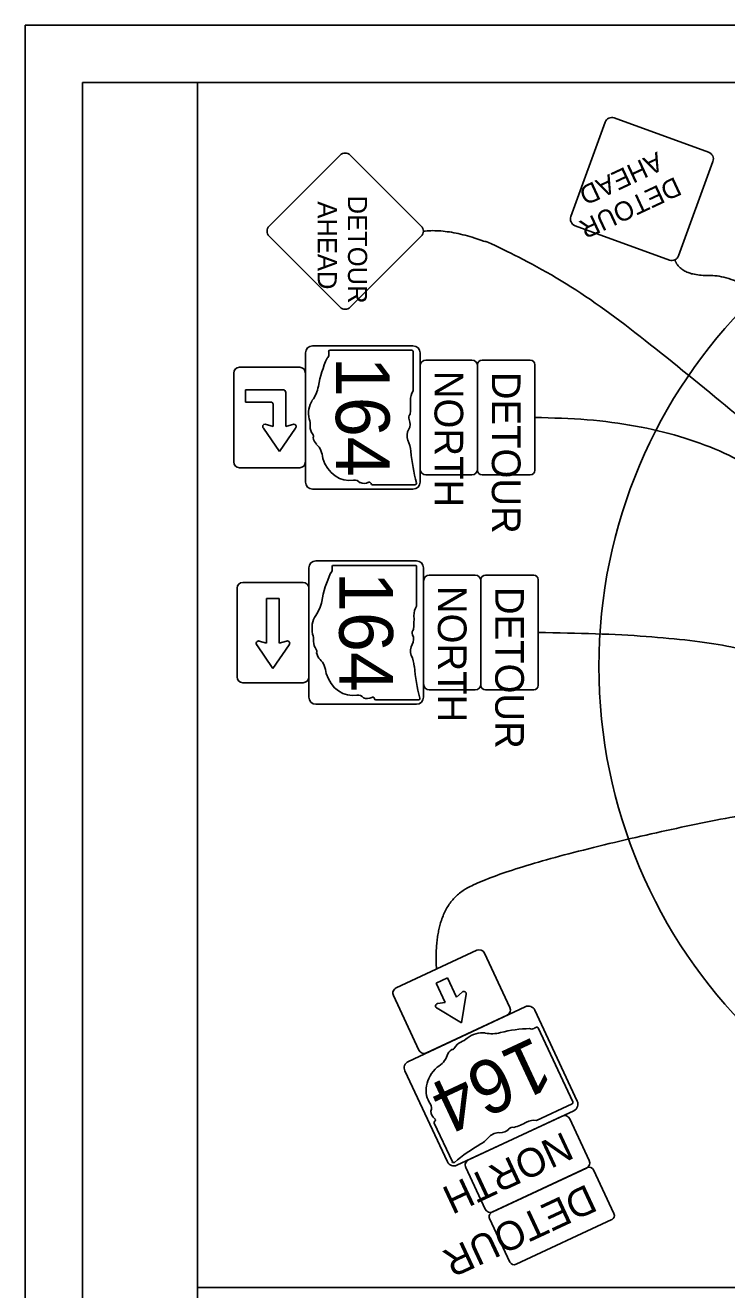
# Model space of a CAD drawing. Extents: x -740 to 1519, y 0 to 440.
# Drawn here: x 0 to 122.3, y 219.6 to 440 of the extents above; entities that cross this region are included whole.
import ezdxf

# ---------------------------------------------------------------- set-up
doc = ezdxf.new("R2010")
doc.units = 0
for name, color, linetype in [('GM_X_Minor_Lake', 7, 'Continuous'), ('GM_X_Minor_Lake_Text', 7, 'Continuous'), ('GM_X_Minor_River', 7, 'Continuous'), ('GM_X_Section', 7, 'Continuous'), ('SH_Border', 7, 'Continuous'), ('SH_Cut_Line', 7, 'Continuous'), ('SH_Data', 7, 'Continuous')]:
    doc.layers.add(name, color=color, linetype=linetype)

msp = doc.modelspace()

# ---------------------------------------------------------------- linework, layer by layer
at = {"layer": 'GM_X_Minor_Lake'}
for p, q in [((36.93, 326.4), (36.93, 341.9)), ((37.93, 342.9), (48.43, 342.9)), ((49.43, 341.9), (49.43, 326.4)), ((44.27, 340.08), (42.08, 340.08)), ((42.08, 340.08), (42.08, 332.27)), ((44.27, 332.27), (44.27, 340.08)), ((40.38, 331.98), (43.18, 327.9)), ((42.08, 332.27), (40.8, 332.67)), ((43.18, 327.9), (46.02, 332.03)), ((45.55, 332.67), (44.27, 332.27)), ((48.43, 325.4), (37.93, 325.4))]:
    msp.add_line(p, q, dxfattribs=at)
for centre, radius, start, end in [((37.93, 341.9), 1, 90, 180), ((48.43, 341.9), 1, 360, 90), ((40.68, 332.27), 0.417, 72.7954, 225.0096), ((45.68, 332.27), 0.417, 325.4112, 107.2046), ((37.93, 326.4), 1, 180, 270), ((48.43, 326.4), 1, 270, 360)]:
    msp.add_arc(centre, radius, start, end, dxfattribs=at)
at = {"layer": 'GM_X_Minor_Lake_Text'}
msp.add_line((30, 430), (350, 430), dxfattribs=at)
at = {"layer": 'GM_X_Minor_River'}
for p, q in [((67.36, 383.35), (53.13, 383.35)), ((67.61, 376.26), (67.61, 383.12)), ((69.84, 381.64), (77.84, 381.64)), ((36.34, 379.38), (36.34, 363.88)), ((47.84, 380.38), (37.34, 380.38)), ((48.84, 363.88), (48.84, 379.38)), ((68.84, 362.64), (68.84, 380.64)), ((78.84, 380.64), (78.84, 362.64)), ((38.37, 374.29), (38.37, 376.48)), ((38.37, 376.48), (44.93, 376.48)), ((45.4, 376.01), (45.4, 370.07)), ((45.4, 376.01), (45.4, 376.01)), ((42.9, 374.29), (38.37, 374.29)), ((43.21, 370.07), (43.21, 373.98)), ((41.8, 370.49), (43.21, 370.07)), ((45.4, 370.07), (46.8, 370.49)), ((44.3, 365.7), (41.51, 369.78)), ((47.1, 369.78), (44.3, 365.7)), ((37.34, 362.88), (47.84, 362.88)), ((77.84, 361.64), (69.84, 361.64)), ((60.52, 359.92), (67.96, 359.92)), ((60.52, 359.92), (60.52, 359.92)), ((67.96, 345.86), (53.73, 345.86)), ((68.2, 338.77), (68.2, 345.63)), ((70.43, 344.15), (78.43, 344.15)), ((69.43, 325.15), (69.43, 343.15)), ((79.43, 343.15), (79.43, 325.15)), ((78.43, 324.15), (70.43, 324.15)), ((61.11, 322.43), (68.55, 322.43)), ((61.11, 322.43), (61.11, 322.43)), ((64.66, 272.21), (78.7, 278.77)), ((80.03, 278.28), (84.48, 268.77)), ((71.62, 273.04), (73.6, 273.97)), ((73.6, 273.97), (75.19, 270.57)), ((73.2, 269.65), (71.62, 273.04)), ((75.19, 270.57), (76.18, 271.47)), ((68.62, 261.37), (64.18, 270.88)), ((71.87, 269.46), (73.2, 269.65)), ((76.87, 271.1), (76.05, 266.14)), ((83.99, 267.44), (69.95, 260.88)), ((76.05, 266.14), (71.79, 268.66)), ((95.43, 252.33), (89.41, 265.23)), ((89.1, 249.11), (95.32, 252.01)), ((77.28, 242.23), (93.59, 249.85)), ((94.92, 249.36), (98.3, 242.12)), ((71.3, 248.62), (74.45, 241.87)), ((71.3, 248.62), (71.3, 248.62)), ((80.18, 233.65), (76.79, 240.9)), ((97.82, 240.79), (81.51, 233.17))]:
    msp.add_line(p, q, dxfattribs=at)
for points in [[(102.68, 423.86), (119.12, 417.87)], [(95.09, 406.67), (101.08, 423.11)], [(42.52, 404.99), (54.89, 417.37)], [(56.66, 417.37), (69.03, 404.99)], [(119.87, 416.27), (113.89, 399.83)], [(112.28, 399.08), (95.84, 405.06)], [(54.89, 390.85), (42.52, 403.23)], [(69.03, 403.23), (56.66, 390.85)], [(50.09, 384.13), (67.59, 384.13)], [(48.84, 360.38), (48.84, 382.88)], [(68.84, 382.88), (68.84, 360.38)], [(88.04, 381.64), (79.64, 381.64)], [(78.84, 380.84), (78.84, 362.44)], [(88.84, 362.44), (88.84, 380.84)], [(79.64, 361.64), (88.04, 361.64)], [(67.59, 359.13), (50.09, 359.13)], [(50.68, 346.65), (68.18, 346.65)], [(49.43, 322.9), (49.43, 345.4)], [(69.43, 345.4), (69.43, 322.9)], [(88.63, 344.15), (80.23, 344.15)], [(79.43, 343.35), (79.43, 324.95)], [(89.43, 324.95), (89.43, 343.35)], [(80.23, 324.15), (88.63, 324.15)], [(68.18, 321.65), (50.68, 321.65)], [(66.78, 259.4), (87.16, 268.92)], [(88.83, 268.32), (96.23, 252.46)], [(73.58, 241.88), (66.17, 257.74)], [(95.63, 250.8), (75.24, 241.28)], [(98, 240.87), (81.33, 233.09)], [(102.62, 232.87), (99.06, 240.48)], [(80.94, 232.02), (84.49, 224.41)], [(85.56, 224.03), (102.23, 231.81)]]:
    msp.add_lwpolyline(points, dxfattribs=at)
for centre, radius, start, end in [((102.25, 422.68), 1.25, 69.9975, 159.9975), ((55.77, 416.48), 1.25, 45, 135), ((118.7, 416.7), 1.25, 339.9975, 69.9975), ((96.27, 406.24), 1.25, 159.9975, 249.9975), ((43.4, 404.11), 1.25, 135, 225), ((68.15, 404.11), 1.25, 315, 45), ((112.71, 400.25), 1.25, 249.9975, 339.9975), ((55.77, 391.74), 1.25, 225, 315), ((50.09, 382.88), 1.25, 90, 180), ((67.59, 382.88), 1.25, 360, 90), ((69.84, 380.64), 1, 90, 180), ((77.84, 380.64), 1, 360, 90), ((79.64, 380.84), 0.8, 90, 180), ((88.04, 380.84), 0.8, 360, 90), ((37.34, 379.38), 1, 90, 180), ((47.84, 379.38), 1, 360, 90), ((44.93, 376.01), 0.469, 360, 90), ((42.9, 373.98), 0.312, 360, 90), ((41.8, 370.07), 0.417, 89.9983, 224.9999), ((46.8, 370.07), 0.417, 315.0001, 89.9983), ((37.34, 363.88), 1, 180, 270), ((47.84, 363.88), 1, 270, 360), ((69.84, 362.64), 1, 180, 270), ((77.84, 362.64), 1, 270, 360), ((79.64, 362.44), 0.8, 180, 270), ((88.04, 362.44), 0.8, 270, 360), ((50.09, 360.38), 1.25, 180, 270), ((67.59, 360.38), 1.25, 270, 360), ((50.68, 345.4), 1.25, 90, 180), ((68.18, 345.4), 1.25, 360, 90), ((70.43, 343.15), 1, 90, 180), ((78.43, 343.15), 1, 360, 90), ((80.23, 343.35), 0.8, 90, 180), ((88.63, 343.35), 0.8, 360, 90), ((70.43, 325.15), 1, 180, 270), ((78.43, 325.15), 1, 270, 360), ((80.23, 324.95), 0.8, 180, 270), ((88.63, 324.95), 0.8, 270, 360), ((50.68, 322.9), 1.25, 180, 270), ((68.18, 322.9), 1.25, 270, 360), ((79.13, 277.86), 1, 25.0285, 115.0285), ((65.08, 271.3), 1, 115.0285, 205.0285), ((76.46, 271.17), 0.417, 350.4397, 132.2331), ((71.93, 269.05), 0.417, 97.8239, 250.038), ((87.69, 267.79), 1.25, 25.0285, 115.0285), ((83.57, 268.35), 1, 295.0285, 25.0285), ((69.53, 261.79), 1, 205.0285, 295.0285), ((67.31, 258.27), 1.25, 115.0285, 205.0285), ((95.1, 251.93), 1.25, 295.0285, 25.0285), ((94.01, 248.94), 1, 25.0285, 115.0285), ((74.71, 242.41), 1.25, 205.0285, 295.0285), ((77.7, 241.33), 1, 115.0285, 205.0285), ((97.4, 241.69), 1, 295.0285, 25.0285), ((98.34, 240.15), 0.8, 25.0285, 115.0285), ((81.09, 234.08), 1, 205.0285, 295.0285), ((81.67, 232.36), 0.8, 115.0285, 205.0285), ((101.89, 232.53), 0.8, 295.0285, 25.0285), ((85.22, 224.75), 0.8, 205.0285, 295.0285)]:
    msp.add_arc(centre, radius, start, end, dxfattribs=at)
for centre, major_axis, start_param, end_param in [((65.1, 373.1), (0, -17.95), 4.195997, 4.488961), ((52.31, 382.61), (0, -0.754), 0.519207, 1.627899), ((54.56, 383.04), (0, -2.09), 4.665946, 4.897461), ((53.1, 383.08), (0, -0.274), 3.00124, 4.508301), ((67.39, 383.09), (0, -0.272), 1.712693, 3.28349), ((46.74, 378.45), (0, -5.62), 0.823519, 1.323587), ((69.26, 374.62), (0, -2.63), 4.042523, 4.731795), ((52.24, 372.37), (0, -3.56), 4.026481, 4.996735), ((59.62, 373.75), (0, -9.45), 1.404758, 1.657858), ((47.32, 370.32), (0, -2.93), 1.495662, 1.94098), ((67.47, 371.61), (0, -0.76), 3.836095, 5.185415), ((65.82, 370.49), (0, -1.58), 0.950623, 2.079405), ((51.18, 370.06), (0, -1.9), 4.691044, 5.507374), ((49.8, 368.34), (0, -0.535), 1.147584, 2.315152), ((51.75, 368.57), (0, -2.01), 4.937069, 5.64225), ((68.08, 368.45), (0, -1.9), 4.081561, 5.145723), ((49.14, 364.25), (0, -3.4), 1.647645, 2.488434), ((63.26, 365.1), (0, -5), 1.699011, 2.107814), ((56.45, 366.87), (0, -6.22), 5.101752, 6.440018), ((87.01, 368.27), (0, -24.85), 4.814394, 5.042369), ((57.4, 358.98), (0, -1.76), 2.387724, 3.262537), ((59.03, 362.55), (0, -2.42), 5.934695, 6.695948), ((59.97, 359.98), (0, -0.404), 1.883978, 3.671073), ((60.49, 360.2), (0, -0.279), 5.05454, 6.418171), ((67.99, 360.18), (0, -0.261), 6.141152, 7.989035), ((65.69, 335.61), (0, -17.95), 4.195997, 4.488961), ((52.9, 345.12), (0, -0.754), 0.519207, 1.627899), ((55.15, 345.55), (0, -2.09), 4.665946, 4.897461), ((53.69, 345.59), (0, -0.274), 3.00124, 4.508301), ((67.99, 345.6), (0, -0.272), 1.712693, 3.28349), ((47.33, 340.96), (0, -5.62), 0.823519, 1.323587), ((69.85, 337.14), (0, -2.63), 4.042523, 4.731795), ((52.83, 334.89), (0, -3.56), 4.026481, 4.996735), ((60.21, 336.26), (0, -9.45), 1.404758, 1.657858), ((47.91, 332.83), (0, -2.93), 1.495662, 1.94098), ((68.06, 334.12), (0, -0.76), 3.836095, 5.185415), ((66.42, 333), (0, -1.58), 0.950623, 2.079405), ((51.77, 332.57), (0, -1.9), 4.691044, 5.507374), ((50.39, 330.85), (0, -0.535), 1.147584, 2.315152), ((52.35, 331.08), (0, -2.01), 4.937069, 5.64225), ((68.67, 330.96), (0, -1.9), 4.081561, 5.145723), ((49.73, 326.76), (0, -3.4), 1.647645, 2.488434), ((63.85, 327.61), (0, -5), 1.699011, 2.107814), ((57.05, 329.38), (0, -6.22), 5.101752, 6.440018), ((87.6, 330.78), (0, -24.85), 4.814394, 5.042369), ((57.99, 321.49), (0, -1.76), 2.387724, 3.262537), ((59.62, 325.06), (0, -2.42), 5.934695, 6.695948), ((60.56, 322.49), (0, -0.404), 1.883978, 3.671073), ((61.08, 322.71), (0, -0.279), 5.05454, 6.418171), ((68.58, 322.69), (0, -0.261), 6.141152, 7.989035), ((79.08, 261.39), (-3.23, -1.51), 4.026481, 4.996735), ((85.18, 250.05), (-16.26, -7.59), 4.195997, 4.488961), ((88.39, 265.66), (-0.683, -0.319), 0.519207, 1.627899), ((89.73, 263.8), (-1.89, -0.88), 4.665946, 4.897461), ((89.15, 265.14), (-0.248, -0.116), 3.00124, 4.508301), ((76.53, 261.37), (-1.72, -0.8), 4.691044, 5.507374), ((75.14, 264.98), (-2.65, -1.24), 1.495662, 1.94098), ((82.26, 268.94), (-5.09, -2.38), 0.823519, 1.323587), ((70.41, 260.76), (-3.09, -1.44), 1.647645, 2.488434), ((75.42, 260.22), (-1.82, -0.85), 4.937069, 5.64225), ((74.39, 261.9), (-0.484, -0.226), 1.147584, 2.315152), ((75.88, 255.24), (-5.63, -2.63), 5.101752, 6.440018), ((69.13, 251.05), (-1.6, -0.75), 2.387724, 3.262537), ((95.2, 252.19), (-0.246, -0.115), 1.712693, 3.28349), ((73.05, 251.08), (-2.2, -1.03), 5.934695, 6.695948), ((71.12, 249.14), (-0.366, -0.171), 1.883978, 3.671073), ((88.32, 246.92), (-2.39, -1.11), 4.042523, 4.731795), ((71.54, 248.76), (-0.253, -0.118), 5.05454, 6.418171), ((82.23, 245.38), (-1.72, -0.8), 4.081561, 5.145723), ((83.12, 248.28), (-1.43, -0.67), 0.950623, 2.079405), ((84.83, 247.27), (-0.688, -0.321), 3.836095, 5.185415), ((83.45, 255.29), (-8.57, -4), 1.404758, 1.657858), ((90.07, 228.15), (-22.52, -10.52), 4.814394, 5.042369), ((77.15, 248.32), (-4.53, -2.12), 1.699011, 2.107814), ((74.69, 241.96), (-0.236, -0.11), 6.141152, 7.989035)]:
    msp.add_ellipse(centre, major_axis=major_axis, ratio=0.8, start_param=start_param, end_param=end_param, dxfattribs=at)
at = {"layer": 'GM_X_Section'}
msp.add_line((30, 220), (640, 220), dxfattribs=at)
at = {"layer": 'SH_Border'}
for points in [[(10, 430), (30, 430), (30, 10), (10, 10)], [(30, 430), (670, 430), (670, 10), (30, 10)]]:
    msp.add_lwpolyline(points, close=True, dxfattribs=at)
at = {"layer": 'SH_Cut_Line'}
msp.add_lwpolyline([(0, 0), (680, 0), (680, 440), (0, 440)], close=True, dxfattribs=at)
at = {"layer": 'SH_Data'}
msp.add_circle((190, 328.25), 90, dxfattribs=at)
for points in [[(69.4, 404.11), (82.79, 405.62), (141.27, 358.21), (160.83, 339.36), (170.35, 327.23), (180.17, 327)], [(113.24, 399.12), (114.19, 396.29), (124.55, 396.46), (142.54, 382.43), (155.9, 351.48), (182.81, 336.97), (184.21, 332.93)], [(88.84, 371.64), (123.17, 371.48), (153.86, 334.17), (159.8, 322.29), (179.52, 319.82), (184.38, 326.65)], [(89.43, 334.15), (119.97, 333.88), (141.84, 325.02), (157.11, 315.58), (178.04, 314.26), (183.64, 315.77), (188.32, 326.29)], [(71.68, 275.49), (71.08, 286.38), (82.97, 292.81), (119.92, 301.72), (148.58, 305.92), (179.75, 311.29), (189.97, 313.69), (190.53, 320.44)]]:
    msp.add_open_spline(points, degree=2, dxfattribs=at)

# ---------------------------------------------------------------- texts
at = {"layer": 'GM_X_Minor_River'}
for s, height, rotation, p in [('AHEAD', 3.333, 204.9975, (110.17, 418.01)), ('DETOUR', 3.333, 204.9975, (113.3, 413.65)), ('AHEAD', 3.333, 270, (50.98, 409.31)), ('DETOUR', 3.333, 270, (56.26, 410.31)), ('164', 9.375, 270, (54.14, 382.21)), ('NORTH', 5, 270, (71.34, 379.77)), ('DETOUR', 5, 270, (81.34, 379.6)), ('164', 9.375, 270, (54.73, 344.72)), ('NORTH', 5, 270, (71.93, 342.28)), ('DETOUR', 5, 270, (81.93, 342.11)), ('164', 9.375, 205.0285, (88.79, 263.83)), ('NORTH', 5, 205.0285, (93.86, 247.22)), ('DETOUR', 5, 205.0285, (97.94, 238.08))]:
    msp.add_text(s, height=height, rotation=rotation, dxfattribs=at).set_placement(p)

doc.saveas('drawing.dxf')
